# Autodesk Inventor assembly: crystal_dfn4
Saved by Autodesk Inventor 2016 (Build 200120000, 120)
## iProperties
Created: 2018-05
Part Number: crystal_dfn4
Document SubType Name: Assembly
Designer: Administrator
Title: crystal_dfn4 v1
Author: Administrator
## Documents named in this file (5)
- c:\worker\convert-fusion-mar-2018\tmp\job-1\16\output\files\8c58ff39-88bb-4352-afd9-60265520bae5\crystal_dfn4 v1.iam
- c:\worker\convert-fusion-mar-2018\tmp\job-1\16\output\files\8c58ff39-88bb-4352-afd9-60265520bae5\Component2.ipt
- c:\worker\convert-fusion-mar-2018\tmp\job-1\16\output\files\8c58ff39-88bb-4352-afd9-60265520bae5\Component3.ipt
- c:\worker\convert-fusion-mar-2018\tmp\job-1\16\output\files\8c58ff39-88bb-4352-afd9-60265520bae5\Component4.ipt
- c:\worker\convert-fusion-mar-2018\tmp\job-1\16\output\files\8c58ff39-88bb-4352-afd9-60265520bae5\Component5_2.ipt
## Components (4 placed, 4 different names)
1. Component2:1
2. Component3:1
3. Component4:1
4. Component5:1
